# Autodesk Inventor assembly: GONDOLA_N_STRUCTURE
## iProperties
Shininess: 64.0
Length Units: 11272
Angle Units: 11279
Time Units: 11290
Mass Units: 11286
Length Display Precision: 3
Angle Display Precision: 2
Compacted: True
Part Number: GONDOLA_N_STRUCTURE
Document SubType Name: Assembly
Created: 2004-12
Designer: John Blackburn
Manufacturer: Standard
Standards Organization: Custom
Density: 0.0
Volumn: 0.0
Area: 0.0
PropertySet Name: Model Information
Control State: 0
Master: False
Checked Out: False
Author: John Blackburn
